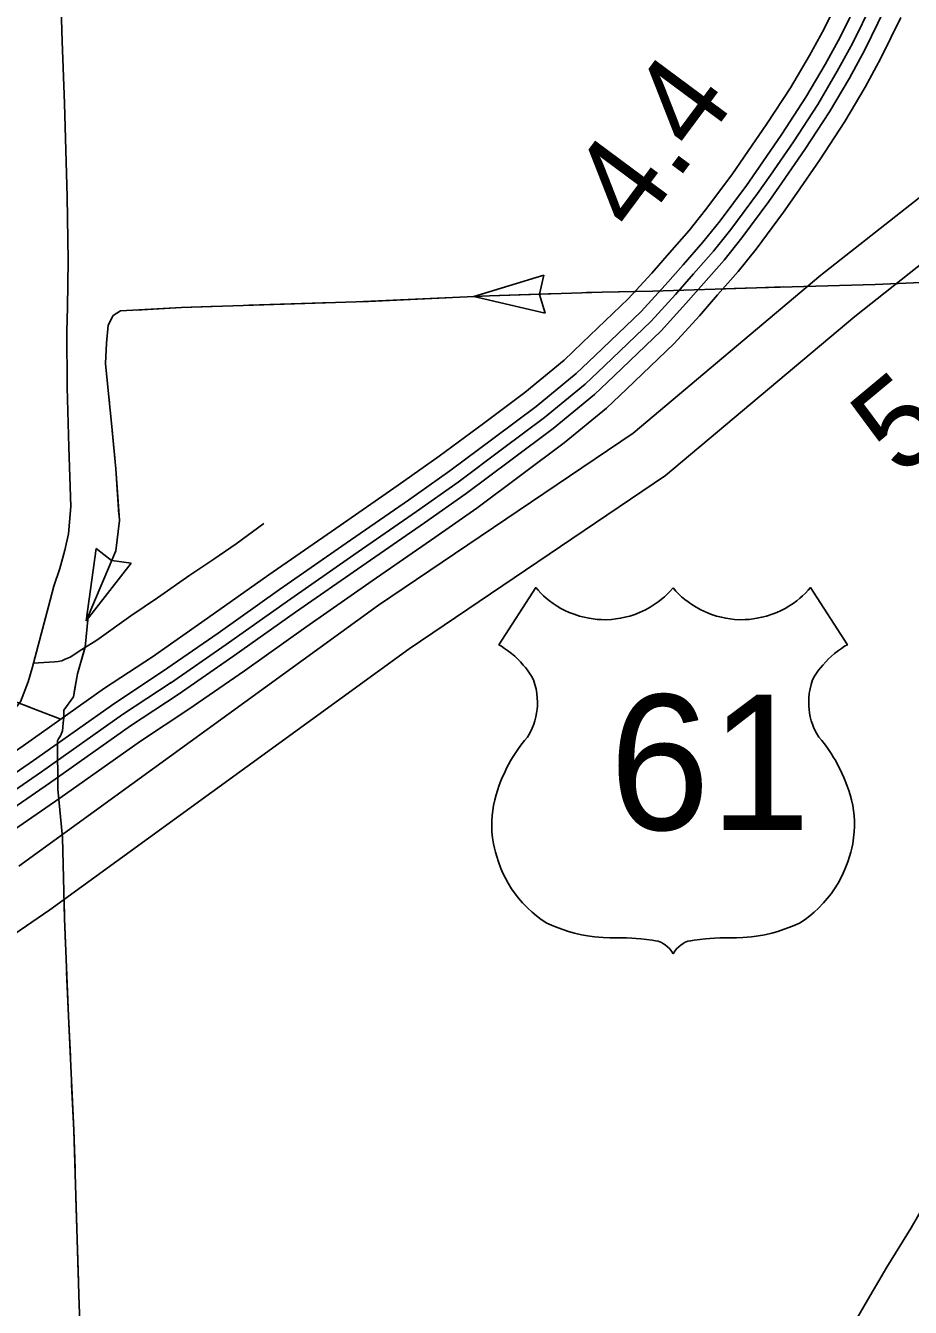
# Model space of a CAD drawing. Extents: x -117616 to 64730, y 54117 to 789866.
# Drawn here: x 63089.6 to 63172.5, y 54758.9 to 54879.2 of the extents above; entities that cross this region are included whole.
import ezdxf

# ---------------------------------------------------------------- set-up
doc = ezdxf.new("R2010")
doc.units = 0
for name, color, linetype in [('10', 7, 'Continuous'), ('15', 7, 'Continuous'), ('19', 7, 'Continuous'), ('22', 7, 'Continuous'), ('33', 7, 'Continuous'), ('40', 7, 'Continuous'), ('43', 7, 'Continuous'), ('48', 7, 'Continuous'), ('R_Draft', 7, 'Continuous')]:
    doc.layers.add(name, color=color, linetype=linetype)

msp = doc.modelspace()

# ---------------------------------------------------------------- linework, layer by layer
at = {"layer": '10'}
for points in [[(63093.73, 54832.58), (63093.84, 54834.06), (63093.66, 54839.61), (63093.5, 54845.24), (63093.46, 54850.49), (63093.52, 54852.73), (63093.61, 54857.12), (63093.5, 54863.1), (63093.25, 54871.85), (63093.04, 54877.7), (63092.85, 54883.89), (63092.67, 54890.79), (63092.58, 54895.11), (63092.49, 54897.51)], [(63039.15, 54780.88), (63043.78, 54783.89), (63050.12, 54787.92), (63054.23, 54790.83), (63058.92, 54794.11), (63064.62, 54798.06), (63068.44, 54800.76), (63074.17, 54804.78), (63078.38, 54807.69), (63083.85, 54811.46), (63086.84, 54813.53), (63088.05, 54814.45), (63088.52, 54815.02), (63089.13, 54815.74), (63089.84, 54817.6), (63090.21, 54818.9), (63091.76, 54824.67), (63092.26, 54826.58), (63092.8, 54828.25), (63093.29, 54829.96), (63093.62, 54831.49), (63093.73, 54832.58)]]:
    msp.add_lwpolyline(points, dxfattribs=at)
at = {"layer": '15'}
for p, q in [((63164.16, 54855.76), (63178.97, 54867.45)), ((63182.24, 54863.66), (63167.32, 54851.88)), ((63146.56, 54840.94), (63164.16, 54855.76)), ((63167.32, 54851.88), (63149.58, 54836.95)), ((63122.69, 54824.79), (63146.56, 54840.94)), ((63149.58, 54836.95), (63125.56, 54820.7)), ((63088.98, 54800.32), (63122.69, 54824.79)), ((63125.56, 54820.7), (63091.87, 54796.24)), ((63091.87, 54796.24), (63039.65, 54760.35))]:
    msp.add_line(p, q, dxfattribs=at)
at = {"layer": '19'}
for points in [[(63101.49, 54819.97), (63106.67, 54823.57), (63112.42, 54827.65), (63118.67, 54832), (63124.53, 54836.06), (63128.38, 54838.77), (63132.53, 54841.85), (63136.4, 54844.75), (63140.08, 54847.79), (63141.79, 54849.41), (63146.1, 54853.54), (63148.29, 54855.94), (63149.95, 54857.85), (63151.8, 54859.95), (63153.35, 54861.87), (63155.79, 54865.16), (63156.96, 54866.85), (63159.08, 54869.93), (63161.3, 54873.32), (63163.08, 54876.35), (63164.45, 54878.86), (63166.25, 54882.53)], [(63167.78, 54881.79), (63165.96, 54878.08), (63164.56, 54875.51), (63162.75, 54872.43), (63160.49, 54868.98), (63158.36, 54865.88), (63157.17, 54864.16), (63154.7, 54860.83), (63153.1, 54858.85), (63151.23, 54856.73), (63149.55, 54854.81), (63147.31, 54852.35), (63142.96, 54848.18), (63141.21, 54846.52), (63137.45, 54843.42), (63133.54, 54840.49), (63129.38, 54837.39), (63125.5, 54834.66), (63119.64, 54830.6), (63113.4, 54826.26), (63107.65, 54822.17), (63102.45, 54818.57)], [(63103.91, 54816.42), (63109.14, 54820.05), (63114.89, 54824.13), (63121.12, 54828.46), (63126.99, 54832.53), (63130.9, 54835.28), (63135.1, 54838.41), (63139.05, 54841.37), (63142.94, 54844.57), (63144.76, 54846.3), (63149.18, 54850.54), (63151.49, 54853.08), (63153.18, 54855.01), (63155.09, 54857.17), (63156.75, 54859.24), (63159.28, 54862.65), (63160.5, 54864.4), (63162.65, 54867.53), (63164.96, 54871.06), (63166.82, 54874.23), (63168.27, 54876.88), (63170.12, 54880.65)], [(63171.65, 54879.91), (63169.78, 54876.09), (63168.3, 54873.39), (63166.4, 54870.16), (63164.06, 54866.58), (63161.9, 54863.43), (63160.66, 54861.66), (63158.1, 54858.2), (63156.39, 54856.08), (63154.46, 54853.89), (63152.76, 54851.95), (63150.39, 54849.35), (63145.93, 54845.07), (63144.06, 54843.29), (63140.1, 54840.03), (63136.12, 54837.05), (63131.9, 54833.91), (63127.96, 54831.14), (63122.09, 54827.07), (63115.87, 54822.74), (63110.12, 54818.65), (63104.9, 54815.04)], [(63002.99, 54751.45), (63005.51, 54753.16), (63013.96, 54759.04), (63023.21, 54765.51), (63027.82, 54768.76), (63034.49, 54773.42), (63039.58, 54776.9), (63044.95, 54780.72), (63048.2, 54782.82), (63055.02, 54787.65), (63063.05, 54793.27), (63066.49, 54795.51), (63072.83, 54800.1), (63078.88, 54804.3), (63083.28, 54807.43), (63089.39, 54811.62), (63097, 54817.02), (63101.49, 54819.97)], [(63102.45, 54818.57), (63097.96, 54815.61), (63090.36, 54810.23), (63084.26, 54806.04), (63079.85, 54802.91), (63073.81, 54798.71), (63067.45, 54794.11), (63064, 54791.86), (63055.99, 54786.26), (63049.15, 54781.41), (63045.91, 54779.32), (63040.55, 54775.51), (63035.45, 54772.02), (63028.8, 54767.36), (63024.19, 54764.11), (63014.93, 54757.65), (63006.47, 54751.76), (63003.9, 54750.02), (63002.99, 54751.45)], [(63005.29, 54747.82), (63007.94, 54749.61), (63016.42, 54755.51), (63025.68, 54761.99), (63030.29, 54765.24), (63036.93, 54769.88), (63042.04, 54773.38), (63047.36, 54777.16), (63050.61, 54779.26), (63057.49, 54784.13), (63065.45, 54789.71), (63068.92, 54791.96), (63075.31, 54796.59), (63081.35, 54800.78), (63085.75, 54803.91), (63091.85, 54808.1), (63099.43, 54813.47), (63103.91, 54816.42)], [(63104.9, 54815.04), (63100.38, 54812.06), (63092.82, 54806.7), (63086.72, 54802.51), (63082.33, 54799.39), (63076.3, 54795.2), (63069.88, 54790.56), (63066.4, 54788.3), (63058.47, 54782.74), (63051.56, 54777.85), (63048.32, 54775.75), (63043.01, 54771.98), (63037.9, 54768.48), (63031.27, 54763.84), (63026.66, 54760.59), (63017.39, 54754.12), (63008.9, 54748.21), (63006.2, 54746.38), (63005.29, 54747.82)]]:
    msp.add_lwpolyline(points, dxfattribs=at)
at = {"layer": '22'}
for points in [[(63150.3, 54826.42), (63150.03, 54826.12), (63149.78, 54825.86), (63149.5, 54825.59), (63149.19, 54825.33), (63148.89, 54825.1), (63148.53, 54824.85), (63148.14, 54824.6), (63147.7, 54824.36), (63147.14, 54824.1), (63146.71, 54823.94), (63146.23, 54823.78), (63145.78, 54823.66), (63145.37, 54823.58), (63144.94, 54823.51), (63144.54, 54823.47), (63144, 54823.44), (63143.55, 54823.45), (63143.17, 54823.47), (63142.8, 54823.51), (63142.43, 54823.57), (63141.97, 54823.66), (63141.53, 54823.78), (63141.01, 54823.95), (63140.56, 54824.12), (63140.16, 54824.31), (63139.79, 54824.5), (63139.44, 54824.7), (63139.06, 54824.96), (63138.71, 54825.21), (63138.41, 54825.46), (63138.15, 54825.69), (63137.89, 54825.94), (63137.64, 54826.21), (63137.43, 54826.45), (63133.97, 54821.09), (63134.21, 54820.94), (63134.51, 54820.75), (63134.79, 54820.55), (63135.16, 54820.26), (63135.46, 54820.01), (63135.72, 54819.76), (63135.99, 54819.49), (63136.26, 54819.18), (63136.46, 54818.95), (63136.65, 54818.7), (63136.85, 54818.42), (63137.04, 54818.13), (63137.22, 54817.79), (63137.35, 54817.37), (63137.46, 54816.96), (63137.53, 54816.52), (63137.57, 54816.11), (63137.59, 54815.71), (63137.58, 54815.34), (63137.55, 54815.04), (63137.5, 54814.68), (63137.44, 54814.34), (63137.34, 54813.96), (63137.24, 54813.64), (63137.09, 54813.27), (63136.87, 54812.8), (63136.64, 54812.43), (63136.36, 54812.1), (63136.02, 54811.66), (63135.75, 54811.28), (63135.49, 54810.9), (63135.25, 54810.52), (63135.06, 54810.19), (63134.88, 54809.87), (63134.69, 54809.5), (63134.48, 54809.06), (63134.29, 54808.64), (63134.16, 54808.32), (63134.01, 54807.91), (63133.84, 54807.41), (63133.7, 54807), (63133.58, 54806.55), (63133.46, 54806.02), (63133.39, 54805.55), (63133.33, 54805.06), (63133.3, 54804.53), (63133.3, 54804.03), (63133.32, 54803.54), (63133.38, 54802.97), (63133.47, 54802.42), (63133.56, 54802.01), (63133.65, 54801.65), (63133.77, 54801.24), (63133.93, 54800.73), (63134.16, 54800.12), (63134.35, 54799.66), (63134.58, 54799.2), (63134.83, 54798.74), (63135.16, 54798.21), (63135.5, 54797.73), (63135.82, 54797.31), (63136.19, 54796.88), (63136.67, 54796.38), (63137.08, 54796.01), (63137.5, 54795.66)], [(63150.3, 54826.42), (63150.56, 54826.12), (63150.81, 54825.86), (63151.1, 54825.59), (63151.41, 54825.33), (63151.71, 54825.1), (63152.07, 54824.85), (63152.45, 54824.6), (63152.9, 54824.36), (63153.46, 54824.1), (63153.89, 54823.94), (63154.37, 54823.78), (63154.82, 54823.66), (63155.23, 54823.58), (63155.66, 54823.51), (63156.05, 54823.47), (63156.6, 54823.44), (63157.04, 54823.45), (63157.43, 54823.47), (63157.79, 54823.51), (63158.16, 54823.57), (63158.63, 54823.66), (63159.06, 54823.78), (63159.59, 54823.95), (63160.03, 54824.12), (63160.44, 54824.31), (63160.81, 54824.5), (63161.15, 54824.7), (63161.54, 54824.96), (63161.89, 54825.21), (63162.19, 54825.46), (63162.44, 54825.69), (63162.7, 54825.94), (63162.96, 54826.21), (63163.17, 54826.45), (63166.63, 54821.09), (63166.38, 54820.94), (63166.09, 54820.75), (63165.81, 54820.55), (63165.44, 54820.26), (63165.14, 54820.01), (63164.88, 54819.76), (63164.61, 54819.49), (63164.33, 54819.18), (63164.14, 54818.95), (63163.94, 54818.7), (63163.74, 54818.42), (63163.55, 54818.13), (63163.38, 54817.79), (63163.24, 54817.37), (63163.14, 54816.96), (63163.06, 54816.52), (63163.02, 54816.11), (63163.01, 54815.71), (63163.02, 54815.34), (63163.04, 54815.04), (63163.09, 54814.68), (63163.16, 54814.34), (63163.25, 54813.96), (63163.36, 54813.64), (63163.5, 54813.27), (63163.73, 54812.8), (63163.96, 54812.43), (63164.24, 54812.1), (63164.57, 54811.66), (63164.85, 54811.28), (63165.11, 54810.9), (63165.34, 54810.52), (63165.54, 54810.19), (63165.71, 54809.87), (63165.91, 54809.5), (63166.12, 54809.06), (63166.31, 54808.64), (63166.44, 54808.32), (63166.59, 54807.91), (63166.76, 54807.41), (63166.89, 54807), (63167.02, 54806.55), (63167.13, 54806.02), (63167.21, 54805.55), (63167.27, 54805.06), (63167.3, 54804.53), (63167.3, 54804.03), (63167.28, 54803.54), (63167.22, 54802.97), (63167.13, 54802.42), (63167.04, 54802.01), (63166.95, 54801.65), (63166.83, 54801.24), (63166.67, 54800.73), (63166.44, 54800.12), (63166.24, 54799.66), (63166.01, 54799.2), (63165.76, 54798.74), (63165.44, 54798.21), (63165.1, 54797.73), (63164.77, 54797.31), (63164.4, 54796.88), (63163.92, 54796.38), (63163.52, 54796.01), (63163.1, 54795.66)], [(63137.5, 54795.66), (63137.93, 54795.33), (63138.45, 54794.99), (63139.11, 54794.69), (63139.87, 54794.4), (63140.5, 54794.2), (63141.06, 54794.04), (63141.7, 54793.89), (63142.29, 54793.78), (63142.94, 54793.69), (63143.75, 54793.63), (63144.37, 54793.6), (63144.9, 54793.61), (63145.41, 54793.6), (63145.93, 54793.59), (63146.42, 54793.56), (63146.84, 54793.53), (63147.26, 54793.5), (63147.8, 54793.44), (63148.33, 54793.38), (63148.64, 54793.33), (63148.9, 54793.28), (63149.22, 54793.15), (63149.4, 54793.05), (63149.56, 54792.95), (63149.77, 54792.77), (63149.98, 54792.56), (63150.15, 54792.35), (63150.3, 54792.1)], [(63163.1, 54795.66), (63162.67, 54795.33), (63162.15, 54794.99), (63161.49, 54794.69), (63160.72, 54794.4), (63160.1, 54794.2), (63159.54, 54794.04), (63158.9, 54793.89), (63158.3, 54793.78), (63157.66, 54793.69), (63156.85, 54793.63), (63156.23, 54793.6), (63155.7, 54793.61), (63155.18, 54793.6), (63154.67, 54793.59), (63154.18, 54793.56), (63153.75, 54793.53), (63153.33, 54793.5), (63152.8, 54793.44), (63152.27, 54793.38), (63151.95, 54793.33), (63151.69, 54793.28), (63151.38, 54793.15), (63151.2, 54793.05), (63151.04, 54792.95), (63150.83, 54792.77), (63150.62, 54792.56), (63150.45, 54792.35), (63150.3, 54792.1)]]:
    msp.add_lwpolyline(points, dxfattribs=at)
at = {"layer": '33'}
msp.add_lwpolyline([(63090.33, 54819.37), (63091.8, 54819.44), (63092.33, 54819.48), (63092.65, 54819.51), (63092.99, 54819.59), (63093.32, 54819.74), (63093.77, 54819.93), (63094.87, 54820.64), (63096.29, 54821.51), (63099.48, 54823.79), (63101.97, 54825.48), (63105.01, 54827.6), (63107.24, 54829.12), (63109.35, 54830.55), (63111.93, 54832.47)], dxfattribs=at)
at = {"layer": '40'}
for points in [[(63199.71, 54812.32), (63198.24, 54809.82), (63195.8, 54805.7), (63192.43, 54800), (63189.96, 54795.8), (63186.58, 54790.13), (63183.94, 54785.76), (63181.33, 54781.29), (63178.86, 54777.12), (63175.75, 54771.8), (63174.05, 54768.92), (63172.61, 54766.4), (63170.32, 54762.72), (63168.3, 54759.26), (63166.65, 54756.38), (63165.13, 54753.88), (63163.01, 54750.33), (63161.69, 54748.09), (63160.72, 54746.39), (63159.37, 54744.13), (63158.2, 54742.13), (63156.88, 54739.99)], [(63172.61, 54766.4), (63170.32, 54762.72), (63168.3, 54759.26), (63166.65, 54756.38)]]:
    msp.add_lwpolyline(points, dxfattribs=at)
at = {"layer": '43'}
for p, q in [((63131.62, 54853.75), (63138.19, 54855.75)), ((63138.19, 54855.75), (63137.78, 54853.97)), ((63138.31, 54852.2), (63137.78, 54853.95)), ((63131.62, 54853.75), (63138.31, 54852.2)), ((63095.29, 54823.32), (63096.22, 54830.12)), ((63096.22, 54830.12), (63097.67, 54829)), ((63095.29, 54823.32), (63099.5, 54828.74)), ((63099.5, 54828.74), (63097.69, 54828.99))]:
    msp.add_line(p, q, dxfattribs=at)
for points in [[(63176.41, 54855.19), (63169.25, 54854.88), (63158.13, 54854.57), (63148.41, 54854.26), (63143.64, 54854.16), (63133.09, 54853.8), (63120.6, 54853.24), (63104.21, 54852.73), (63098.5, 54852.39), (63097.82, 54851.96), (63097.35, 54851.05), (63097.2, 54849.37), (63097.11, 54847.45), (63097.39, 54844.63), (63097.68, 54841.56), (63098.06, 54837.58), (63098.4, 54832.74), (63098.06, 54829.91), (63095.48, 54823.78), (63095.19, 54820.85), (63094.47, 54818.36), (63094.09, 54816.21)], [(63139.54, 54854.02), (63133.09, 54853.8), (63131.62, 54853.74)], [(63146.72, 54854.23), (63143.64, 54854.16), (63142.18, 54854.11)], [(63160.65, 54854.64), (63158.13, 54854.57), (63154.97, 54854.47)], [(63107.88, 54852.84), (63104.21, 54852.73), (63099.97, 54852.48)], [(63118.44, 54853.17), (63110.52, 54852.92)], [(63125.03, 54853.44), (63121.08, 54853.26)], [(63128.99, 54853.62), (63125.03, 54853.44)], [(63097.66, 54851.64), (63097.35, 54851.05), (63097.2, 54849.37), (63097.11, 54847.45), (63097.39, 54844.63), (63097.47, 54843.82)], [(63097.72, 54841.19), (63098.06, 54837.58), (63098.36, 54833.3)], [(63098.15, 54830.67), (63098.06, 54829.91), (63095.48, 54823.78), (63095.43, 54823.28)], [(63067.06, 54824.98), (63066.2, 54824.89), (63066.11, 54824.77), (63066.11, 54824.31), (63066.38, 54823.42), (63066.69, 54823.19), (63067.13, 54823.01), (63068.56, 54822.43), (63071.44, 54821.2), (63072.85, 54820.57), (63073.57, 54820.09), (63074.4, 54819.39), (63075.1, 54818.39), (63075.61, 54817.95), (63076.23, 54817.6), (63077.14, 54817.47), (63079.08, 54817.3), (63083.02, 54817.05), (63084.57, 54817.02), (63085.71, 54816.84), (63086.96, 54816.4), (63090.55, 54815.03), (63092.82, 54814.13)], [(63095.14, 54820.66), (63094.47, 54818.36), (63094.2, 54816.82)], [(63094.2, 54816.82), (63094.09, 54816.21)], [(63089.61, 54815.39), (63090.55, 54815.03), (63092.82, 54814.13)], [(63094.09, 54816.21), (63093.2, 54814.94), (63093.18, 54814.28), (63093.13, 54813.72), (63093.07, 54813.03), (63092.89, 54812.54), (63092.69, 54812.25), (63092.6, 54812.09), (63092.64, 54807.53)], [(63094.09, 54816.21), (63093.2, 54814.94), (63093.18, 54814.31)], [(63092.64, 54807.53), (63093.05, 54803.02), (63093.26, 54795.43), (63093.62, 54786.26), (63094.13, 54775.55), (63094.64, 54759.15), (63095, 54750.28), (63095.05, 54748.69), (63094.69, 54747.51), (63094.18, 54746.59), (63093.72, 54746.23), (63092.54, 54746.08), (63088.49, 54745.93), (63079.89, 54745.67), (63071.96, 54745.52), (63068.17, 54745.39)], [(63093.21, 54797.21), (63093.26, 54795.43), (63093.35, 54793.03)], [(63093.45, 54790.39), (63093.62, 54786.26), (63093.8, 54782.48)], [(63093.92, 54779.84), (63094.13, 54775.55), (63094.24, 54771.93)], [(63094.32, 54769.29), (63094.57, 54761.37)]]:
    msp.add_lwpolyline(points, dxfattribs=at)
at = {"layer": 'R_Draft'}
for points in [[(63103.2, 54817.5), (63108.4, 54821.11), (63114.14, 54825.19), (63120.38, 54829.53), (63126.25, 54833.6), (63130.14, 54836.34), (63134.32, 54839.45), (63138.25, 54842.39), (63142.07, 54845.54), (63143.86, 54847.24), (63148.24, 54851.45), (63150.52, 54853.95), (63152.21, 54855.87), (63154.09, 54858.01), (63155.72, 54860.04), (63158.22, 54863.41), (63159.43, 54865.14), (63161.57, 54868.25), (63163.85, 54871.74), (63165.69, 54874.87), (63167.11, 54877.48), (63168.95, 54881.22)], [(63007.21, 54750.69), (63015.67, 54756.58), (63024.93, 54763.05), (63029.55, 54766.3), (63036.19, 54770.95), (63041.29, 54774.44), (63046.64, 54778.24), (63049.88, 54780.34), (63056.74, 54785.2), (63064.73, 54790.79), (63068.19, 54793.03), (63074.56, 54797.65), (63080.6, 54801.84), (63085, 54804.97), (63091.1, 54809.16), (63098.69, 54814.54), (63103.26, 54817.54)]]:
    msp.add_lwpolyline(points, dxfattribs=at)

# ---------------------------------------------------------------- texts
at = {"layer": '22'}
msp.add_text('61', height=12.672, dxfattribs=at).set_placement((63144.32, 54803.73))
at = {"layer": '48'}
for s, rotation, p in [('4.4', 53.3851, (63146.87, 54859.43)), ('5.0', 39.8303, (63171.59, 54836.7))]:
    msp.add_text(s, height=8.448, rotation=rotation, dxfattribs=at).set_placement(p)

doc.saveas('drawing.dxf')
